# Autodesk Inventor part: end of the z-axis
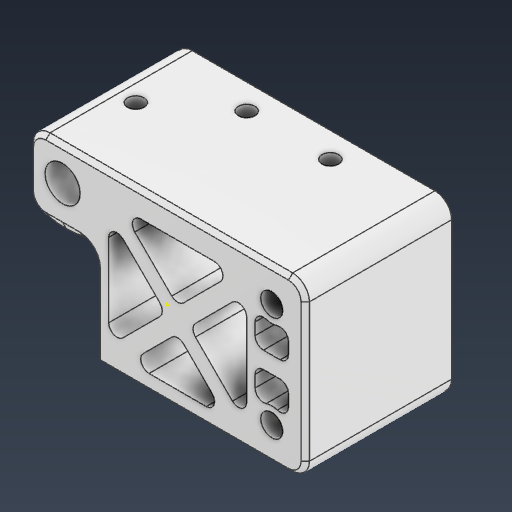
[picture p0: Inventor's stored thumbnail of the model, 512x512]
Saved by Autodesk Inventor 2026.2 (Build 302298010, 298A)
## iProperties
Created: 2026-04
Part Number: end of the z-axis
Material: ABS 플라스틱
Document SubType Name: Modeling
Designer: work
Density: 1.06 g/cm^3
Appearance: 매끄러움 - 흰색
Mass: 57.6498 g
Surface Area: 222.91 cm^2
Volume: 54.3866 cm^3
Author: work
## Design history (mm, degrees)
sketch "스케치1"
  geometry: L1 (-25, -12.5)-(25, -12.5); L2 (25, -12.5)-(25, 12.5); L3 (25, 12.5)-(-25, 12.5); L4 (-25, 12.5)-(-25, -12.5); L5 (-25, -12.5)-(25, 12.5); L6 (25, -12.5)-(-25, 12.5); L7 (33, -20.5)-(-33, -20.5); L8 (-33, -20.5)-(-33, 20.5); L9 (-33, 20.5)-(33, 20.5); L10 (33, 20.5)-(33, -20.5); L11 (33, -20.5)-(-33, 20.5); L12 (-33, -20.5)-(33, 20.5); L13 (-33, 3.5)-(-17, 3.5); L14 (-17, 3.5)-(-17, -12.5); L15 (-17, -12.5)-(-33, -12.5); L16 (-33, -12.5)-(-33, 3.5); L17 (-17, -12.5)-(-17, -20.5); C1 r 4.2 at (-25, 12.5); C2 r 2.65 at (25, 12.5); C3 r 2.65 at (25, -12.5); 2 further points
  constraints: 34 end point, 6 parallel, 4 midpoint, 4 perpendicular, 3 centre point, 3 coincident, 3 horizontal, 3 point on line
  dimensions: "d0" = 50 distance of L2.end L3.end; "d1" = 25 distance of L3.end L1.start; "d2" = 8.4 diameter of C1; "d3" = 5.3 diameter of C2; "d4" = 5.3 diameter of C3; "d5" = 8 distance between parallel lines of L9 L3; "d6" = 8 distance between parallel lines of L10 L2; "d7" = 16 distance of L13.start L13.end; "d8" = 16 distance of L13.end L14.end
extrude "돌출1" new body sketch "스케치1" distance "d9" = 35; taper "d10" = 0 deg
sketch "스케치2"
  geometry: L1 (23, -6)-(43, -6); L2 (33, 0)-(33, -35); L3 (16, -35)-(66, -35) reference; L4 (66, 0)-(0, 0) reference; C1 r 2 at (43, -6); C2 r 2 at (23, -6); 2 further points
  constraints: 4 end point, 2 centre point, 2 coincident, 2 point on line, 1 horizontal, 1 midpoint
  dimensions: "d11" = 20 distance of L1.start L1.end; "d12" = 6 distance between parallel lines of L4 L1; "d13" = 4 diameter of C1; "d14" = 4 diameter of C2
extrude "돌출2" cut sketch "스케치2" distance "d15" = 5; taper "d16" = 0 deg
sketch "스케치3"
  geometry: 1 further point
sketch "스케치4"
  geometry: L1 (35, 37.2)-(35, 28.8) reference; L2 (0, 37.2)-(0, 28.8) reference; L3 (35, 41)-(35, 24) reference; L4 (35, 33)-(0, 33); L5 (35, 0)-(35, 41) reference; L6 (35, 20.5)-(0, 20.5); L7 (0, 41)-(0, 24) reference; L8 (0, 24)-(35, 24) reference; L9 (35, 41)-(35, 24) reference; L10 (0, 41)-(35, 41) reference; L11 (17.5, 20.5)-(17.5, 8); L12 (21.5, 3.5)-(13.5, 3.5); L13 (13.5, 3.5)-(13.5, 12.5); L14 (13.5, 12.5)-(21.5, 12.5); L15 (21.5, 12.5)-(21.5, 3.5); L16 (21.5, 3.5)-(13.5, 12.5); L17 (13.5, 3.5)-(21.5, 12.5); L18 (21.5, 12.5)-(35, 24); L19 (13.5, 12.5)-(0, 24); L20 (35, 0)-(0, 0); L21 (0, 0)-(0, 3.5); L22 (0, 3.5)-(35, 3.5); L23 (35, 3.5)-(35, 0); 1 further point
  constraints: 30 end point, 7 midpoint, 4 parallel, 3 horizontal, 2 perpendicular, 1 point on line, 1 vertical
  dimensions: "d17" = 12.5 distance from line of L6.start L4; "d18" = 12.5 distance of L11.start L11.end; "d19" = 8 distance of L13.end L14.end; "d20" = 9 distance of L12.end L13.end; "d21" = 35 distance between parallel lines of L5 L21
  node "투영된 루프1"
  node "투영된 루프2"
node "작업 평면1"
sketch "스케치5"
  geometry: L1 (35, 33.7)-(35, 24); L2 (0, 42)-(0, 24); L3 (35, 41)-(35, 24); L4 (35, 33)-(0, 33); L5 (35, 0)-(35, 41); L6 (35, 20.5)-(0, 20.5); L7 (0, 41)-(0, 24); L8 (0, 24)-(35, 24); L9 (35, 41)-(35, 24); L10 (0, 41)-(35, 41); L11 (21.5, 3.5)-(13.5, 3.5); L12 (13.5, 3.5)-(13.5, 12.5); L13 (13.5, 12.5)-(21.5, 12.5); L14 (21.5, 12.5)-(21.5, 3.5); L15 (21.5, 3.5)-(13.5, 12.5); L16 (13.5, 3.5)-(21.5, 12.5); L17 (21.5, 12.5)-(35, 24); L18 (13.5, 12.5)-(0, 24); L19 (35, 0)-(0, 0); L20 (0, 0)-(0, 3.5); L21 (0, 3.5)-(35, 3.5); L22 (35, 3.5)-(35, 0); L23 (0, 0)-(0, 41) reference; L24 (0, 41)-(35, 41) reference; L25 (35, 0)-(35, 41) reference; L26 (0, 0)-(35, 0) reference; L27 (0, 24)-(35, 24) reference; L28 (17.5, 12.5)-(17.5, 24); 6 further points
  constraints: 46 end point, 6 midpoint, 5 perpendicular, 4 coincident, 4 parallel, 3 horizontal, 2 point on line, 1 collinear
  dimensions: "d22" = 12.5 distance from line of L6.start L4; "d24" = 8 distance of L12.end L13.end; "d25" = 9 distance of L11.end L12.end; "d26" = 35 distance between parallel lines of L5 L20; "d27" = 35 distance of L2.end L8.end; "d28" = 11.5 distance of L28.start L28.end
revolve "회전1" sketch "스케치5" stored, may be unused: angle "d29" = 90 deg
sketch "스케치6"
  geometry: L1 (-8, 15.564)-(-8, -15.564) reference; A1 r 17.5 centre (0, 0) between (-8, 15.564) and (-8, -15.564) reference; 1 further point
extrude "돌출3" cut sketch "스케치6" extent not by distance; stored distance "d30" = 0; taper "d31" = 0 deg
sketch "스케치7"
  geometry: C1 r 2 at (0, 0); 1 further point
  constraints: 1 centre point
  dimensions: "d32" = 4 diameter of C1
extrude "돌출4" cut sketch "스케치7" extent not by distance; stored distance "d33" = 0; taper "d34" = 0 deg
sketch "스케치8"
  geometry: L1 (35, 24)-(35, 0) reference; L2 (35, 3.5)-(0, 3.5); L3 (0, 0)-(35, 0) reference; L4 (35, 1.75)-(0, 1.75); L5 (0, 24)-(0, 0) reference; C1 r 1.5 at (25, 1.75); C2 r 1.5 at (10, 1.75); 1 further point
  constraints: 5 point on line, 4 end point, 2 centre point, 2 horizontal
  dimensions: "d35" = 35 distance of L2.start L2.end; "d36" = 3.5 distance between parallel lines of L3 L2; "d37" = 1.75 distance between parallel lines of L3 L4; "d38" = 3 diameter of C1; "d39" = 3 diameter of C2; "d40" = 10 distance of L4.start C1.centre; "d41" = 10 distance of L4.end C2.centre
extrude "돌출5" cut sketch "스케치8" distance "d42" = 5; taper "d43" = 0 deg
sketch "스케치9"
  geometry: L1 (0, 24)-(1.936, 24) reference; L2 (0, 24)-(0, 0) reference; L3 (0, 0)-(35, 0) reference; L4 (35, 24)-(35, 0) reference; L5 (33.064, 24)-(35, 24) reference; C1 r 1.5 at (10, 1.75) reference; C2 r 1.5 at (25, 1.75) reference; C3 r 3 at (25, 1.75); C4 r 3 at (10, 1.75); 5 further points
  constraints: 2 centre point, 2 coincident, 1 horizontal alignment
  dimensions: "d44" = 6 diameter of C4; "d45" = 6 diameter of C3
extrude "돌출6" join sketch "스케치9" distance "d46" = 5; taper "d47" = 0 deg
sketch "스케치10"
  geometry: L1 (-19, 14.5)-(14, 14.5); L2 (14, 14.5)-(14, -16.5); L3 (14, -16.5)-(-19, -16.5); L4 (-19, -16.5)-(-19, 14.5); L5 (-33, 20.5)-(33, 20.5) reference; L6 (-33, -20.5)-(-33, 20.5) reference; L7 (17, -20.5)-(-33, -20.5) reference; L8 (17, 3.5)-(17, -20.5) reference; L9 (25, 3.5)-(17, 3.5) reference; L10 (33, 3.5)-(25, 3.5) reference; L11 (33, 20.5)-(33, 3.5) reference; L12 (-19, -15.672)-(11.172, 14.5); L13 (14, 11.672)-(-14.172, -16.5); L14 (-19, 11.672)-(9.172, -16.5); L15 (14, -15.672)-(-16.172, 14.5); L16 (-19, 11.672)-(-16.172, 14.5); L17 (14, 11.672)-(11.172, 14.5); L18 (-29, 12.5)-(-29, -12.5); L19 (-21, -12.5)-(-21, 12.5); L20 (-29, 2)-(-21, 2); L21 (-21, -2)-(-29, -2); L22 (-28.992, 0)-(-21, 0); C1 r 4.2 at (25, 12.5) reference; C2 r 2.65 at (-25, 12.5) reference; C3 r 2.65 at (-25, -12.5) reference; A1 r 4 centre (-25, 12.5) between (-29, 12.5) and (-21, 12.5); A2 r 4 centre (-25, -12.5) between (-29, -12.5) and (-21, -12.5); 5 further points
  constraints: 30 end point, 18 point on line, 5 parallel, 4 perpendicular, 4 point on circle, 2 centre point, 2 coincident, 2 tangent, 2 vertical, 1 horizontal, 1 midpoint
  dimensions: "d48" = 4 distance between parallel lines of L15 L14; "d49" = 4 distance between parallel lines of L13 L12; "d50" = 4 distance between parallel lines of L7 L3; "d51" = 6 distance between parallel lines of L5 L1; "d52" = 3 distance between parallel lines of L8 L2; "d53" = 6 distance from line of C3.centre L4; "d54" = 45 deg angle of L3 L14; "d55" = 45 deg angle of L3 L13; "d56" = 8 diameter of A1; "d57" = 8 diameter of A2; "d58" = 2 distance between parallel lines of L20 L22; "d59" = 4 distance between parallel lines of L21 L20
extrude "돌출7" cut sketch "스케치10" extent not by distance; stored distance "d60" = 0; taper "d61" = 0 deg
fillet "모깎기1" dims "d62" = 2
fillet "모깎기2" dims "d63" = 4
sketch "스케치11"
  geometry: L1 (4, -30.563)-(20, -30.563); L2 (20, -30.563)-(20, -22.563); L3 (20, -22.563)-(4, -22.563); L4 (4, -22.563)-(4, -30.563); L5 (4, -26.563)-(20, -26.563); L6 (12, -22.563)-(12, -26.563); C1 r 1.5 at (7.8, -26.563); C2 r 1.5 at (16.2, -26.563); 1 further point
  constraints: 12 end point, 4 midpoint, 2 centre point, 2 parallel, 1 coincident, 1 horizontal, 1 perpendicular, 1 point on line, 1 symmetric about line, 1 other
  dimensions: "d64" = 3 diameter of C1; "d67" = 8.4 distance of C2.centre C1.centre; "d68" = 16 distance of L1.start L1.end; "d69" = 8 distance of L1.end L2.end
extrude "돌출8" join sketch "스케치11" stored distance "d65" = 5; taper "d66" = 0 deg
fillet "모깎기3" dims "d70" = 4
fillet "모깎기4" dims "d71" = 1.22
chamfer "모따기1" distance "d72" = 1; stored, may be unused: second distance "d73" = 2, angle "d74" = 45 deg
node "솔리드1"
node "투영된 루프3"
node "투영된 루프4"
node "투영된 루프5"
node "투영된 루프6"
